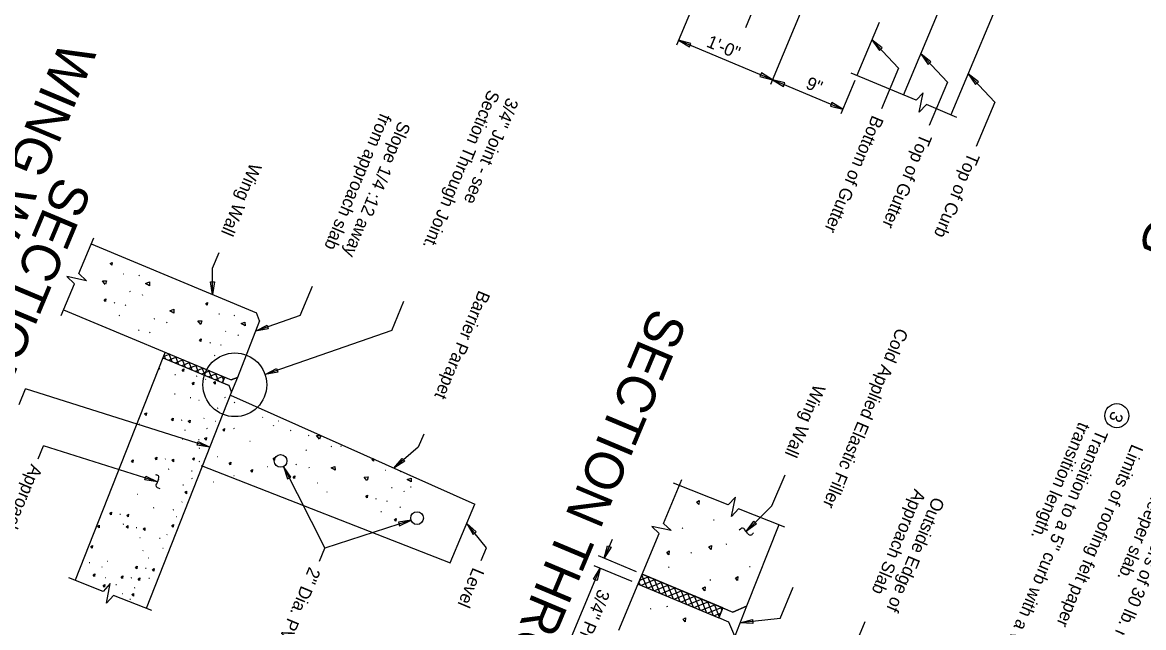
# Model space of a CAD drawing. Extents: x 1968564 to 1968711, y 796599 to 796794.
# Drawn here: x 1968596.99 to 1968641.02, y 796627.75 to 796651.53 of the extents above; entities that cross this region are included whole.
import ezdxf

# ---------------------------------------------------------------- set-up
doc = ezdxf.new("R2010")
doc.units = 0
for name, color, linetype in [('BR_AUTO DIMENSION', 7, 'Continuous'), ('BR_CONCRETE', 7, 'Continuous'), ('BR_DETAILS', 7, 'Continuous'), ('BR_TABLE LINES', 7, 'Continuous'), ('BR_TEXT', 7, 'Continuous')]:
    doc.layers.add(name, color=color, linetype=linetype)

# ---------------------------------------------------------------- blocks, each defined once
blk = doc.blocks.new('B')
at = {"layer": 'BR_AUTO DIMENSION'}
blk.add_lwpolyline([(-0.2, 0.03), (0, 0), (-0.2, -0.03)], close=True, dxfattribs=at)
blk = doc.blocks.new('ARROW')
at = {"layer": 'BR_AUTO DIMENSION', "xscale": 0.625, "yscale": 0.625}
blk.add_blockref('B', (0, 0), dxfattribs=at)

msp = doc.modelspace()

# ---------------------------------------------------------------- linework, layer by layer
at = {"layer": 'BR_AUTO DIMENSION'}
for p, q in [((1968625.174, 796656.597), (1968622.675, 796650.638)), ((1968625.393, 796651.33), (1968627.408, 796656.134)), ((1968628.863, 796655.05), (1968626.363, 796649.091)), ((1968622.752, 796650.824), (1968629.208, 796648.116)), ((1968630.348, 796650.835), (1968631.397, 796649.734)), ((1968632.266, 796650.285), (1968633.315, 796649.184)), ((1968631.397, 796649.734), (1968630.726, 796648.137)), ((1968629.683, 796649.25), (1968629.13, 796647.93)), ((1968633.315, 796649.184), (1968632.596, 796647.472)), ((1968634.126, 796649.5), (1968635.174, 796648.399)), ((1968635.174, 796648.399), (1968634.442, 796646.654)), ((1968604.462, 796641.868), (1968604.72, 796642.483)), ((1968604.455, 796640.839), (1968604.462, 796641.868)), ((1968607.901, 796640.007), (1968608.385, 796641.163)), ((1968611.493, 796639.426), (1968611.975, 796640.574)), ((1968607.901, 796640.007), (1968606.15, 796639.399)), ((1968611.493, 796639.426), (1968606.519, 796637.697)), ((1968596.86, 796636.522), (1968597.114, 796637.128)), ((1968604.351, 796634.845), (1968597.114, 796637.128)), ((1968612.753, 796635.355), (1968612.539, 796634.845)), ((1968597.607, 796634.387), (1968597.821, 796634.897)), ((1968602.295, 796633.485), (1968597.821, 796634.897)), ((1968612.539, 796634.845), (1968611.574, 796634.019)), ((1968607.245, 796634.079), (1968608.87, 796630.875)), ((1968626.425, 796632.539), (1968626.938, 796633.76)), ((1968625.413, 796631.531), (1968626.425, 796632.539)), ((1968612.254, 796631.976), (1968608.87, 796630.875)), ((1968615.221, 796630.892), (1968614.439, 796631.848)), ((1968620.153, 796631.215), (1968619.843, 796630.478)), ((1968608.655, 796630.361), (1968608.87, 796630.875)), ((1968615.008, 796630.383), (1968615.221, 796630.892)), ((1968621.102, 796629.95), (1968619.613, 796630.574)), ((1968615.525, 796620.181), (1968619.68, 796630.089)), ((1968620.939, 796629.561), (1968619.45, 796630.185)), ((1968626.742, 796628.113), (1968627.254, 796629.335)), ((1968626.742, 796628.113), (1968625.173, 796627.937)), ((1968629.567, 796626.744), (1968630.091, 796627.993))]:
    msp.add_line(p, q, dxfattribs=at)
for points in [[(1968623.243, 796650.699), (1968622.752, 796650.824), (1968623.185, 796650.561)], [(1968630.752, 796650.531), (1968630.348, 796650.835), (1968630.645, 796650.426)], [(1968632.67, 796649.982), (1968632.266, 796650.285), (1968632.563, 796649.876)], [(1968625.951, 796649.401), (1968626.441, 796649.276), (1968626.009, 796649.539)], [(1968626.931, 796649.152), (1968626.441, 796649.276), (1968626.873, 796649.014)], [(1968634.53, 796649.196), (1968634.126, 796649.5), (1968634.423, 796649.091)], [(1968628.718, 796648.24), (1968629.208, 796648.116), (1968628.776, 796648.379)], [(1968604.534, 796641.339), (1968604.455, 796640.839), (1968604.384, 796641.34)], [(1968606.647, 796639.492), (1968606.15, 796639.399), (1968606.598, 796639.634)], [(1968607.016, 796637.79), (1968606.519, 796637.697), (1968606.967, 796637.932)], [(1968603.896, 796635.067), (1968604.351, 796634.845), (1968603.851, 796634.924)], [(1968612.003, 796634.287), (1968611.574, 796634.019), (1968611.905, 796634.401)], [(1968601.841, 796633.707), (1968602.295, 796633.485), (1968601.796, 796633.564)], [(1968614.813, 796631.509), (1968614.439, 796631.848), (1968614.697, 796631.414)], [(1968625.824, 796631.831), (1968625.416, 796631.533), (1968625.719, 796631.937)], [(1968620.106, 796630.91), (1968619.843, 796630.478), (1968619.968, 796630.968)], [(1968619.418, 796629.657), (1968619.68, 796630.089), (1968619.556, 796629.598)], [(1968625.678, 796627.918), (1968625.173, 796627.937), (1968625.661, 796628.067)]]:
    msp.add_lwpolyline(points, close=True, dxfattribs=at)
msp.add_circle((1968639.966, 796636.078), 0.472, dxfattribs=at)
at = {"layer": 'BR_CONCRETE'}
for p, q in [((1968631.59, 796648.674), (1968636.85, 796661.214)), ((1968639.037, 796661.209), (1968633.452, 796647.893)), ((1968630.638, 796651.526), (1968629.763, 796649.44)), ((1968599.699, 796642.834), (1968606.18, 796640.116)), ((1968598.611, 796640.241), (1968605.191, 796637.481)), ((1968606.309, 796639.807), (1968606.179, 796640.116)), ((1968606.309, 796639.802), (1968605.433, 796637.583)), ((1968602.511, 796638.351), (1968599.058, 796629.612)), ((1968602.511, 796638.351), (1968605.105, 796637.263)), ((1968602.511, 796638.351), (1968602.511, 796638.351)), ((1968604.931, 796637.59), (1968604.845, 796637.372)), ((1968605.209, 796637.016), (1968605.105, 796637.263)), ((1968605.433, 796637.583), (1968605.191, 796637.481)), ((1968605.209, 796637.016), (1968601.847, 796628.509)), ((1968605.166, 796636.888), (1968614.752, 796632.596)), ((1968605.277, 796637.191), (1968605.277, 796637.191)), ((1968604.006, 796634.121), (1968613.785, 796630.291)), ((1968613.785, 796630.291), (1968614.752, 796632.596)), ((1968626.694, 796631.794), (1968625.429, 796628.592)), ((1968621.333, 796629.853), (1968624.884, 796628.363)), ((1968624.495, 796628.527), (1968624.34, 796628.134)), ((1968625.429, 796628.592), (1968624.884, 796628.363))]:
    msp.add_line(p, q, dxfattribs=at)
for centre in [(1968607.131, 796634.302), (1968612.492, 796632.053)]:
    msp.add_circle(centre, 0.25, dxfattribs=at)
at = {"layer": 'BR_DETAILS'}
for p, q in [((1968632.086, 796648.465), (1968629.532, 796649.537)), ((1968633.681, 796647.797), (1968632.487, 796648.298)), ((1968599.205, 796641.657), (1968599.796, 796643.065)), ((1968600.959, 796641.646), (1968600.981, 796641.65)), ((1968598.515, 796640.01), (1968599.037, 796641.256)), ((1968601.584, 796641.569), (1968601.562, 796641.591)), ((1968601.217, 796640.959), (1968601.239, 796640.963)), ((1968601.725, 796640.797), (1968601.704, 796640.82)), ((1968600.623, 796640.499), (1968600.602, 796640.521)), ((1968601.055, 796640.407), (1968601.034, 796640.429)), ((1968600.791, 796640.018), (1968600.813, 796640.022)), ((1968602.17, 796639.886), (1968602.192, 796639.891)), ((1968604.708, 796640.073), (1968604.73, 796640.078)), ((1968605.332, 796639.996), (1968605.311, 796640.019)), ((1968601.576, 796639.426), (1968601.555, 796639.449)), ((1968602.678, 796639.725), (1968602.657, 796639.747)), ((1968602.008, 796639.335), (1968601.987, 796639.357)), ((1968604.965, 796639.386), (1968604.987, 796639.391)), ((1968605.473, 796639.225), (1968605.452, 796639.247)), ((1968604.372, 796638.926), (1968604.351, 796638.949)), ((1968604.803, 796638.835), (1968604.782, 796638.857)), ((1968604.54, 796638.445), (1968604.562, 796638.45)), ((1968602.382, 796637.922), (1968602.404, 796637.927)), ((1968602.984, 796637.689), (1968603.006, 796637.694)), ((1968603.829, 796637.632), (1968603.851, 796637.637)), ((1968604.178, 796637.503), (1968604.2, 796637.508)), ((1968602.968, 796636.937), (1968602.99, 796636.942)), ((1968603.586, 796636.787), (1968603.608, 796636.792)), ((1968604.94, 796636.794), (1968604.962, 796636.799)), ((1968603.915, 796636.688), (1968603.937, 796636.692)), ((1968604.651, 796636.378), (1968604.673, 796636.382)), ((1968605.329, 796636.582), (1968605.308, 796636.604)), ((1968604.113, 796635.97), (1968604.135, 796635.975)), ((1968606.414, 796636.008), (1968606.436, 796636.013)), ((1968601.575, 796635.758), (1968601.597, 796635.762)), ((1968603.238, 796635.905), (1968603.26, 796635.909)), ((1968603.369, 796635.514), (1968603.391, 796635.519)), ((1968604.235, 796635.577), (1968604.257, 796635.581)), ((1968604.559, 796635.862), (1968604.581, 796635.867)), ((1968605.294, 796635.578), (1968605.316, 796635.583)), ((1968606.87, 796635.665), (1968606.849, 796635.687)), ((1968607.029, 796635.876), (1968607.051, 796635.88)), ((1968607.526, 796635.502), (1968607.548, 796635.506)), ((1968603.273, 796635.156), (1968603.295, 796635.161)), ((1968603.907, 796635.14), (1968603.929, 796635.145)), ((1968605.92, 796635.078), (1968605.942, 796635.082)), ((1968608.209, 796635.313), (1968608.237, 796635.305)), ((1968603.936, 796634.808), (1968603.958, 796634.813)), ((1968608.147, 796634.707), (1968608.126, 796634.73)), ((1968609.117, 796634.871), (1968609.139, 796634.876)), ((1968609.502, 796634.886), (1968609.524, 796634.891)), ((1968602.595, 796634.373), (1968602.617, 796634.378)), ((1968603.932, 796634.281), (1968603.954, 796634.286)), ((1968604.647, 796634.471), (1968604.669, 796634.475)), ((1968607.754, 796634.153), (1968607.733, 796634.176)), ((1968602.213, 796633.766), (1968602.263, 796633.752)), ((1968602.727, 796633.983), (1968602.749, 796633.988)), ((1968603.632, 796633.907), (1968603.654, 796633.912)), ((1968605.289, 796633.723), (1968605.311, 796633.727)), ((1968606.611, 796634.079), (1968606.633, 796634.083)), ((1968608.271, 796634.014), (1968608.25, 796634.036)), ((1968611.234, 796633.939), (1968611.256, 796633.943)), ((1968611.858, 796633.862), (1968611.837, 796633.885)), ((1968602.338, 796633.578), (1968602.252, 796633.392)), ((1968603.292, 796633.362), (1968603.314, 796633.367)), ((1968603.65, 796633.615), (1968603.672, 796633.62)), ((1968604.479, 796633.479), (1968604.501, 796633.483)), ((1968608.561, 796633.437), (1968608.583, 796633.442)), ((1968612.235, 796633.288), (1968612.262, 796633.28)), ((1968622.169, 796631.847), (1968622.892, 796633.571)), ((1968624.712, 796632.577), (1968622.561, 796633.427)), ((1968601.495, 796632.994), (1968601.517, 796632.998)), ((1968602.322, 796633.241), (1968602.387, 796633.22)), ((1968608.944, 796633.085), (1968608.966, 796633.089)), ((1968611.491, 796633.252), (1968611.514, 796633.257)), ((1968612, 796633.091), (1968611.978, 796633.113)), ((1968602.144, 796632.464), (1968602.166, 796632.469)), ((1968603.249, 796632.685), (1968603.271, 796632.69)), ((1968610.898, 796632.792), (1968610.877, 796632.815)), ((1968611.329, 796632.701), (1968611.308, 796632.723)), ((1968611.84, 796632.471), (1968611.819, 796632.494)), ((1968626.934, 796631.699), (1968625.116, 796632.418)), ((1968600.817, 796632.211), (1968600.839, 796632.215)), ((1968602.912, 796632.382), (1968602.934, 796632.387)), ((1968603.024, 796632.117), (1968603.046, 796632.121)), ((1968611.066, 796632.311), (1968611.088, 796632.315)), ((1968624.129, 796631.988), (1968624.162, 796631.98)), ((1968600.949, 796631.82), (1968600.971, 796631.825)), ((1968601.466, 796631.681), (1968601.488, 796631.686)), ((1968622.928, 796631.642), (1968622.896, 796631.675)), ((1968625.186, 796631.625), (1968625.136, 796631.578)), ((1968625.474, 796631.448), (1968625.352, 796631.613)), ((1968601.598, 796631.291), (1968601.62, 796631.296)), ((1968602.377, 796631.265), (1968602.399, 796631.27)), ((1968602.658, 796631.4), (1968602.68, 796631.405)), ((1968620.41, 796627.652), (1968622.001, 796631.447)), ((1968625.698, 796631.467), (1968625.663, 796631.431)), ((1968601.718, 796630.773), (1968601.74, 796630.778)), ((1968602.504, 796630.869), (1968602.526, 796630.874)), ((1968623.271, 796630.674), (1968623.239, 796630.708)), ((1968624.624, 796631.036), (1968624.657, 796631.043)), ((1968599.614, 796630.306), (1968599.636, 796630.31)), ((1968600.328, 796630.364), (1968600.35, 796630.369)), ((1968601.941, 796630.493), (1968601.963, 796630.498)), ((1968600.109, 796630.14), (1968600.131, 796630.145)), ((1968601.826, 796630.086), (1968601.848, 796630.091)), ((1968622.388, 796630.112), (1968622.357, 796630.146)), ((1968625.539, 796630.148), (1968625.572, 796630.154)), ((1968600.168, 796629.173), (1968598.818, 796629.706)), ((1968600.238, 796629.718), (1968600.26, 796629.723)), ((1968600.664, 796629.447), (1968600.686, 796629.452)), ((1968601.263, 796629.71), (1968601.285, 796629.715)), ((1968601.395, 796629.32), (1968601.417, 796629.325)), ((1968601.958, 796629.696), (1968601.98, 796629.7)), ((1968623.986, 796629.624), (1968624.019, 796629.631)), ((1968602.072, 796628.421), (1968600.572, 796629.013)), ((1968600.905, 796629.087), (1968600.928, 796629.092)), ((1968601.217, 796628.869), (1968601.239, 796628.874)), ((1968621.652, 796628.49), (1968621.685, 796628.497)), ((1968622.3, 796628.584), (1968622.333, 796628.591))]:
    msp.add_line(p, q, dxfattribs=at)
for points in [[(1968632.487, 796648.298), (1968632.204, 796647.998), (1968632.369, 796648.765), (1968632.086, 796648.465)], [(1968600.501, 796641.994), (1968600.443, 796642.059), (1968600.511, 796642.098), (1968600.501, 796641.994)], [(1968599.205, 796641.657), (1968599.505, 796641.374), (1968598.737, 796641.539), (1968599.037, 796641.256)], [(1968600.248, 796641.235), (1968600.134, 796641.374), (1968600.294, 796641.378), (1968600.249, 796641.238)], [(1968601.987, 796641.179), (1968601.832, 796641.271), (1968601.982, 796641.33), (1968601.988, 796641.182)], [(1968600.255, 796640.561), (1968600.197, 796640.625), (1968600.265, 796640.665), (1968600.255, 796640.561)], [(1968604.249, 796640.422), (1968604.192, 796640.486), (1968604.259, 796640.526), (1968604.249, 796640.422)], [(1968602.941, 796640.107), (1968602.786, 796640.199), (1968602.935, 796640.257), (1968602.941, 796640.11)], [(1968603.996, 796639.663), (1968603.882, 796639.802), (1968604.043, 796639.806), (1968603.998, 796639.666)], [(1968605.736, 796639.607), (1968605.581, 796639.699), (1968605.731, 796639.757), (1968605.736, 796639.61)], [(1968604.003, 796638.988), (1968603.946, 796639.053), (1968604.013, 796639.093), (1968604.003, 796638.988)], [(1968603.319, 796637.812), (1968603.26, 796637.875), (1968603.326, 796637.916), (1968603.319, 796637.812)], [(1968603.715, 796637.286), (1968603.656, 796637.35), (1968603.723, 796637.391), (1968603.715, 796637.286)], [(1968604.556, 796637.316), (1968604.498, 796637.379), (1968604.564, 796637.42), (1968604.556, 796637.316)], [(1968601.852, 796636.084), (1968601.793, 796636.148), (1968601.859, 796636.189), (1968601.852, 796636.084)], [(1968602.901, 796635.878), (1968602.842, 796635.942), (1968602.909, 796635.982), (1968602.901, 796635.878)], [(1968603.566, 796635.794), (1968603.508, 796635.857), (1968603.574, 796635.898), (1968603.566, 796635.794)], [(1968604.921, 796635.464), (1968604.862, 796635.528), (1968604.929, 796635.569), (1968604.921, 796635.464)], [(1968604.208, 796635.115), (1968604.149, 796635.178), (1968604.216, 796635.219), (1968604.208, 796635.115)], [(1968608.66, 796635.153), (1968608.545, 796635.293), (1968608.706, 796635.296), (1968608.661, 796635.156)], [(1968601.331, 796634.237), (1968601.272, 796634.301), (1968601.338, 796634.341), (1968601.331, 796634.237)], [(1968602.259, 796634.347), (1968602.2, 796634.41), (1968602.267, 796634.451), (1968602.259, 796634.347)], [(1968602.924, 796634.262), (1968602.865, 796634.326), (1968602.932, 796634.367), (1968602.924, 796634.262)], [(1968603.725, 796634.324), (1968603.666, 796634.387), (1968603.733, 796634.428), (1968603.725, 796634.324)], [(1968605.165, 796634.149), (1968605.107, 796634.213), (1968605.175, 796634.253), (1968605.165, 796634.149)], [(1968606.895, 796634.333), (1968606.836, 796634.397), (1968606.903, 796634.438), (1968606.895, 796634.333)], [(1968610.775, 796634.288), (1968610.718, 796634.352), (1968610.785, 796634.392), (1968610.775, 796634.288)], [(1968606.021, 796633.86), (1968605.963, 796633.924), (1968606.031, 796633.964), (1968606.021, 796633.86)], [(1968607.679, 796633.608), (1968607.622, 796633.672), (1968607.689, 796633.712), (1968607.679, 796633.608)], [(1968609.27, 796633.935), (1968609.115, 796634.026), (1968609.265, 796634.085), (1968609.27, 796633.938)], [(1968610.523, 796633.529), (1968610.408, 796633.668), (1968610.569, 796633.672), (1968610.524, 796633.532)], [(1968612.262, 796633.473), (1968612.107, 796633.565), (1968612.257, 796633.623), (1968612.262, 796633.476)], [(1968603.43, 796633.007), (1968603.371, 796633.07), (1968603.437, 796633.111), (1968603.43, 796633.007)], [(1968610.529, 796632.854), (1968610.472, 796632.919), (1968610.539, 796632.958), (1968610.529, 796632.854)], [(1968625.116, 796632.418), (1968624.839, 796632.112), (1968624.988, 796632.883), (1968624.712, 796632.577)], [(1968623.55, 796632.589), (1968623.464, 796632.686), (1968623.565, 796632.745), (1968623.55, 796632.589)], [(1968600.481, 796632.184), (1968600.422, 796632.248), (1968600.489, 796632.288), (1968600.481, 796632.184)], [(1968601.146, 796632.1), (1968601.087, 796632.163), (1968601.154, 796632.204), (1968601.146, 796632.1)], [(1968611.66, 796631.938), (1968611.603, 796632.002), (1968611.67, 796632.042), (1968611.66, 796631.938)], [(1968600.001, 796631.668), (1968599.942, 796631.731), (1968600.008, 796631.772), (1968600.001, 796631.668)], [(1968601.13, 796631.655), (1968601.071, 796631.718), (1968601.138, 796631.759), (1968601.13, 796631.655)], [(1968601.795, 796631.57), (1968601.736, 796631.634), (1968601.803, 796631.675), (1968601.795, 796631.57)], [(1968602.915, 796631.703), (1968602.856, 796631.767), (1968602.922, 796631.808), (1968602.915, 796631.703)], [(1968622.169, 796631.847), (1968622.469, 796631.564), (1968621.702, 796631.729), (1968622.001, 796631.447)], [(1968599.738, 796630.876), (1968599.679, 796630.94), (1968599.746, 796630.98), (1968599.738, 796630.876)], [(1968622.38, 796630.611), (1968622.292, 796630.706), (1968622.392, 796630.768), (1968622.38, 796630.611)], [(1968624.039, 796630.825), (1968623.951, 796630.92), (1968624.051, 796630.981), (1968624.039, 796630.825)], [(1968599.829, 796629.766), (1968599.77, 796629.83), (1968599.836, 796629.87), (1968599.829, 796629.766)], [(1968600.927, 796629.684), (1968600.868, 796629.747), (1968600.934, 796629.788), (1968600.927, 796629.684)], [(1968601.49, 796630.059), (1968601.431, 796630.123), (1968601.498, 796630.164), (1968601.49, 796630.059)], [(1968602.155, 796629.975), (1968602.096, 796630.038), (1968602.163, 796630.079), (1968602.155, 796629.975)], [(1968625.076, 796629.604), (1968624.988, 796629.699), (1968625.087, 796629.76), (1968625.076, 796629.604)], [(1968600.221, 796629.34), (1968600.162, 796629.404), (1968600.228, 796629.445), (1968600.221, 796629.34)], [(1968600.572, 796629.013), (1968600.295, 796628.708), (1968600.444, 796629.479), (1968600.168, 796629.173)], [(1968601.592, 796629.599), (1968601.533, 796629.663), (1968601.6, 796629.704), (1968601.592, 796629.599)], [(1968623.783, 796629.204), (1968623.696, 796629.301), (1968623.797, 796629.36), (1968623.783, 796629.204)], [(1968601.352, 796628.992), (1968601.293, 796629.055), (1968601.359, 796629.096), (1968601.352, 796628.992)], [(1968623.022, 796627.984), (1968622.934, 796628.08), (1968623.033, 796628.141), (1968623.022, 796627.984)]]:
    msp.add_lwpolyline(points, dxfattribs=at)
msp.add_circle((1968605.335, 796637.291), 1.252, dxfattribs=at)
for centre, radius, start, end in [((1968602.239, 796633.638), 0.116, 328.6905, 78.4893), ((1968602.341, 796633.342), 0.103, 151.1353, 259.4209), ((1968625.265, 796631.559), 0.103, 32.3941, 140.6796), ((1968625.574, 796631.506), 0.116, 209.9492, 319.7481)]:
    msp.add_arc(centre, radius, start, end, dxfattribs=at)
at = {"layer": 'BR_TABLE LINES'}
for p, q in [((1968602.597, 796638.569), (1968602.511, 796638.351)), ((1968602.782, 796638.491), (1968602.525, 796638.386)), ((1968602.549, 796638.448), (1968602.605, 796638.312)), ((1968603.043, 796638.382), (1968602.736, 796638.256)), ((1968602.74, 796638.509), (1968602.865, 796638.202)), ((1968603.304, 796638.272), (1968602.997, 796638.147)), ((1968603.001, 796638.4), (1968603.126, 796638.093)), ((1968603.565, 796638.163), (1968603.258, 796638.038)), ((1968603.262, 796638.29), (1968603.387, 796637.983)), ((1968603.523, 796638.181), (1968603.648, 796637.874)), ((1968603.826, 796638.054), (1968603.519, 796637.928)), ((1968604.086, 796637.944), (1968603.78, 796637.819)), ((1968603.783, 796638.071), (1968603.909, 796637.765)), ((1968604.347, 796637.835), (1968604.04, 796637.709)), ((1968604.044, 796637.962), (1968604.17, 796637.655)), ((1968604.608, 796637.725), (1968604.301, 796637.6)), ((1968604.305, 796637.853), (1968604.43, 796637.546)), ((1968604.566, 796637.743), (1968604.691, 796637.436)), ((1968604.869, 796637.616), (1968604.562, 796637.491)), ((1968604.854, 796637.394), (1968604.823, 796637.381)), ((1968604.827, 796637.634), (1968604.89, 796637.479)), ((1968621.311, 796629.801), (1968621.507, 796629.322)), ((1968621.542, 796629.765), (1968621.768, 796629.213)), ((1968621.202, 796629.54), (1968621.246, 796629.432)), ((1968621.584, 796629.748), (1968621.228, 796629.602)), ((1968621.845, 796629.638), (1968621.293, 796629.412)), ((1968622.106, 796629.529), (1968621.554, 796629.303)), ((1968621.803, 796629.656), (1968622.028, 796629.104)), ((1968622.367, 796629.419), (1968621.814, 796629.193)), ((1968622.063, 796629.547), (1968622.289, 796628.994)), ((1968622.627, 796629.31), (1968622.075, 796629.084)), ((1968622.324, 796629.437), (1968622.55, 796628.885)), ((1968622.585, 796629.328), (1968622.811, 796628.775)), ((1968622.888, 796629.201), (1968622.336, 796628.975)), ((1968623.149, 796629.091), (1968622.597, 796628.865)), ((1968622.846, 796629.218), (1968623.072, 796628.666)), ((1968623.41, 796628.982), (1968622.858, 796628.756)), ((1968623.107, 796629.109), (1968623.333, 796628.557)), ((1968623.671, 796628.872), (1968623.119, 796628.646)), ((1968623.368, 796629), (1968623.593, 796628.447)), ((1968623.628, 796628.89), (1968623.854, 796628.338)), ((1968623.932, 796628.763), (1968623.379, 796628.537)), ((1968624.192, 796628.654), (1968623.64, 796628.428)), ((1968623.889, 796628.781), (1968624.115, 796628.229)), ((1968624.453, 796628.544), (1968623.901, 796628.318)), ((1968624.15, 796628.671), (1968624.355, 796628.171)), ((1968624.411, 796628.562), (1968624.461, 796628.44)), ((1968624.41, 796628.31), (1968624.162, 796628.209))]:
    msp.add_line(p, q, dxfattribs=at)
for points in [[(1968605.433, 796637.583), (1968605.209, 796637.016), (1968605.105, 796637.263), (1968604.845, 796637.372), (1968604.931, 796637.59), (1968605.195, 796637.486)], [(1968625.429, 796628.592), (1968624.963, 796627.415), (1968624.729, 796627.971), (1968624.34, 796628.134), (1968624.495, 796628.527), (1968624.884, 796628.363)]]:
    msp.add_lwpolyline(points, close=True, dxfattribs=at)
msp.add_lwpolyline([(1968621.333, 796629.853), (1968621.17, 796629.464), (1968624.34, 796628.134), (1968624.495, 796628.527), (1968621.333, 796629.853)], dxfattribs=at)

# ---------------------------------------------------------------- block references
at = {"layer": 'BR_AUTO DIMENSION'}
for p, xscale, yscale, rotation in [((1968607.245, 796634.079), 3.9999999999, -3.9999999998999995, 116.89882869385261), ((1968612.254, 796631.976), 3.9999999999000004, -3.9999999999, 18.0312044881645)]:
    msp.add_blockref('ARROW', p, dxfattribs=dict(at, xscale=xscale, yscale=yscale, rotation=rotation))

# ---------------------------------------------------------------- texts
for s, rotation, p in [('1\'-0"', 337.246, (1968623.82, 796650.584)), ('9"', 337.246, (1968627.715, 796648.951)), ('3/4" Preformed Joint Filler', 247.246, (1968619.621, 796629.3))]:
    msp.add_text(s, height=0.5, rotation=rotation, dxfattribs=at).set_placement(p)
at = {"layer": 'BR_TEXT'}
for s, height, p in [('SECTION G-G', 1.5, (1968645.898, 796654.826)), ('WING WALL  APPROACH SLAB', 1.5, (1968598.522, 796650.871)), ('Section Through Joint. ', 0.5, (1968615.292, 796648.913)), ('3/4" Joint - see ', 0.5, (1968616.03, 796648.604)), ('from approach slab', 0.5, (1968611.048, 796647.99)), ('Bottom of Gutter', 0.49995, (1968630.369, 796647.909)), ('Slope 1/4 :12 away', 0.5, (1968611.786, 796647.681)), ('Top of Gutter', 0.49995, (1968632.263, 796647.197)), ('Top of Curb', 0.49995, (1968634.138, 796646.448)), ('Wing Wall', 0.5, (1968605.942, 796646.04)), ('SECTION THROUGH', 1.5, (1968598.361, 796645.546)), ('Barrier Parapet', 0.5, (1968614.917, 796641.032)), ('SECTION THROUGH JOINT', 1.5, (1968621.739, 796640.378)), ('Cold Applied Elastic Filler', 0.5, (1968631.335, 796639.559)), ('Wing Wall', 0.5, (1968628.081, 796637.345)), ('3', 0.5, (1968639.785, 796636.291)), ('transition length.', 0.49995, (1968638.483, 796635.86)), ('Transition to a 5" curb with a vertical face at bridge end, 1\'-0" (Min.) ', 0.49995, (1968639.174, 796635.57)), ('Limits of roofing felt paper', 0.49995, (1968640.558, 796634.99)), ('Approach Slab', 0.5, (1968597.338, 796634.203)), ('and sleeper slab.', 0.49995, (1968641.941, 796634.41)), ('Place 2 layers of 30 lb. roofing felt paper between approach slab ', 0.49995, (1968642.632, 796634.12)), ('Approach Slab', 0.5, (1968632.024, 796633.227)), ('Outside Edge of ', 0.5, (1968632.762, 796632.918)), ('For Schedule of Reinforcement, Quantities, and Additional Notes and ', 0.49995, (1968647.193, 796632.287)), ('2" Dia. PVC Conduit', 0.5, (1968608.255, 796630.164)), ('Level', 0.5, (1968614.687, 796630.142))]:
    msp.add_text(s, height=height, rotation=247.246, dxfattribs=at).set_placement(p)

doc.saveas('drawing.dxf')
